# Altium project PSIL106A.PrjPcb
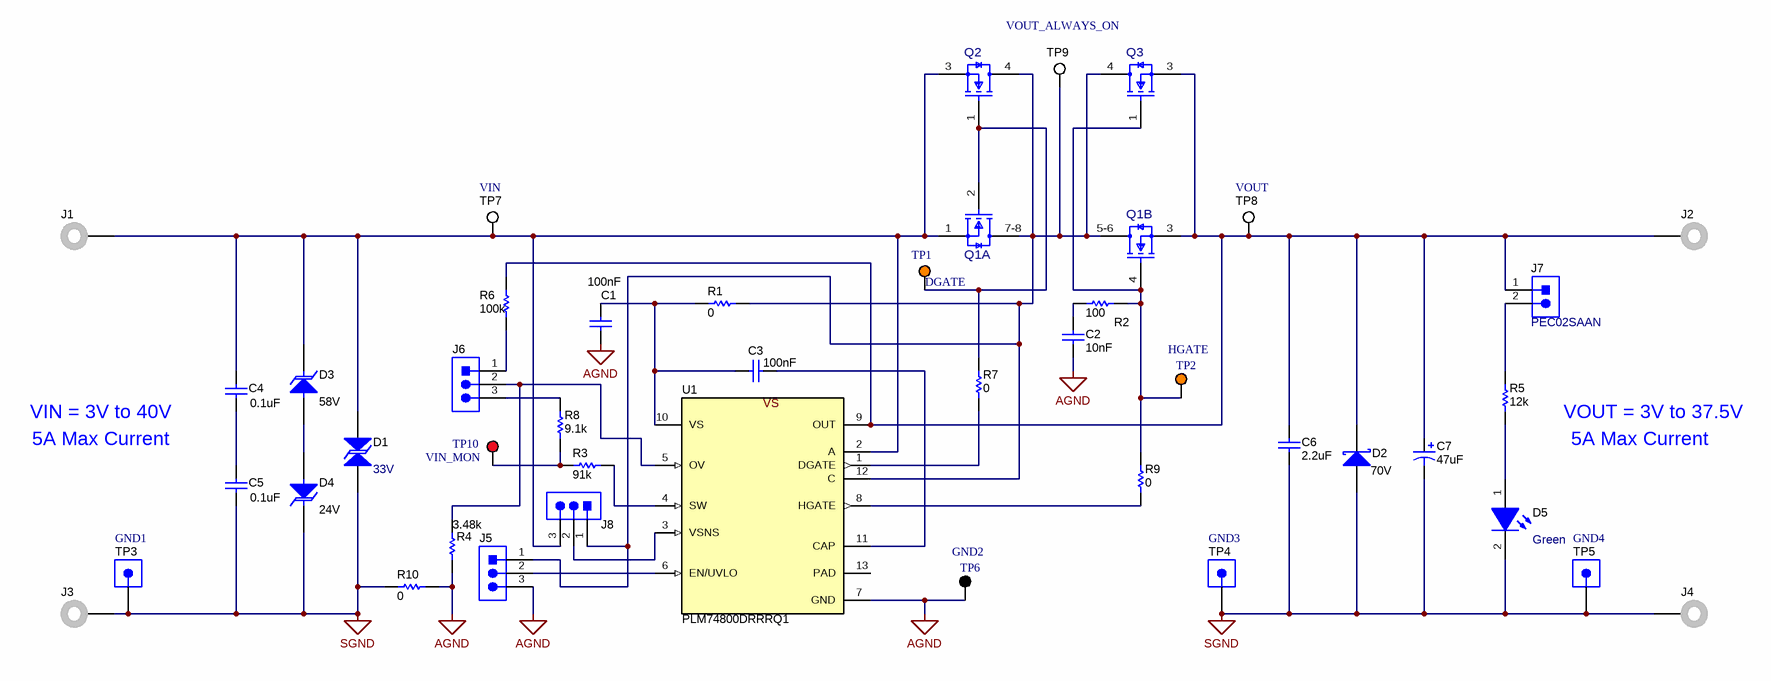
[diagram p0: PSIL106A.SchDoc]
CopyrightYear: 2019; PCB_Layout: Tessolve; PCB_Rev: A; PRJ_Customer: Public Release; PRJ_Engineer: Karikalan Selvaraj; PRJ_Number: PSIL106; PRJ_Title: LM74800EVM-CD; SCH_Rev: A; TechSupport: http://www.ti.com/support; TID: N/A
2 sheets, 64 parts. Net scope: global (net labels, ports and power ports of the same name join across sheets).
Board file: PSIL106A.PcbDoc
Sheets:
  PSIL106A.SchDoc
  PSIL106A_HW.SchDoc

## Sheet PSIL106A.SchDoc
size 431 x 279 mm; Date: Not shown in title block; ApprovedBy: Not shown in title block; CheckedBy: Not shown in title block; Author: Not shown in title block; CompanyName: Not shown in title block; Engineer: Not shown in title block; Organization: Not shown in title block; Address1: Not shown in title block; Address2: Not shown in title block; Address3: Not shown in title block; Address4: Not shown in title block; DocumentNumber: 1; Revision: Use project parameter SCH_Rev; SheetNumber: 1; SheetTotal: 2; PageSetup: Record=PageOptions¦CenterHorizontal=True¦CenterVertical=True¦PrintScale=0.62¦XCorrection=1.00¦YCorrection=1.00¦PrintKind=0¦BorderSize=5000000¦LeftOffset=0¦BottomOffset=0¦Orientation=2¦PaperLength=1000¦PaperWidth=1000¦Scale=100¦PaperSource=15¦PrintQuality=600¦MediaType=1¦DitherType=10¦PrintScaleMode=1¦PaperKind=Letter

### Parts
C1  Cap_F: 100nF  [0603]  (hidden comment: GRM188R72A104KA35J)
C2  Cap_F: 10nF  [0603]  (hidden comment: CGA3E2X7R2A103K080AA)
C3  Cap_F: 100nF  [0603]  (hidden comment: CGA3E2X7R1E104K080AA)
C4  ValueDisplayed: 0.1uF  [1206_180]  (hidden comment: CGA5L2X7R2A104K160AA)
C5  ValueDisplayed: 0.1uF  [1206_180]  (hidden comment: CGA5L2X7R2A104K160AA)
C6  ValueDisplayed: 2.2uF  [1210_210]  (hidden comment: CMP-0009084-1)
C7  ValueDisplayed: 47uF  [SM_RADIAL_F]  (hidden comment: EEE-FK1J470P)
D1  value 33V  [SMB-Bi]  (hidden comment: SMBJ33CA-13-F)
D2  value 70V  [SMA]  (hidden comment: B170-13-F)
D3  value 58V  [SMB]  (hidden comment: CMP-0005583-3)
D4  value 24V  [SMB]  (hidden comment: CMP-0005557-4)
D5  value Green  [LED_LTST-C190]  (hidden comment: LTST-C190GKT)
J1  CMP-0055166-2  [Keystone575-8]  (value not drawn)
J2  CMP-0055166-2  [Keystone575-8]  (value not drawn)
J3  CMP-0055166-2  [Keystone575-8]  (value not drawn)
J4  CMP-0055166-2  [Keystone575-8]  (value not drawn)
J5  PEC03SAAN  [CONN_PEC03SAAN]  (value not drawn)
J6  PEC03SAAN  [CONN_PEC03SAAN]  (value not drawn)
J7  PEC02SAAN  [CONN_PEC02SAAN]
J8  PEC03SAAN  [CONN_PEC03SAAN]  (value not drawn)
Q1  NVMFD5C672NLT1G  [FP-NVMFD5C672NLT1G_DFN8_5X6-MFG]  (value not drawn)  (parts A,B of 2)
Q2  IPD100N06S4-03  [FP-IPD100N06S4-03_PG-TO252-3-MFG]  (value not drawn)
Q3  IPD100N06S4-03  [FP-IPD100N06S4-03_PG-TO252-3-MFG]  (value not drawn)
R1  ValueDisplayed: 0  [0402]  (hidden comment: RK73Z1ETTP)
R2  ValueDisplayed: 100  [0603]  (hidden comment: CRCW0603100RJNEA)
R3  ValueDisplayed: 91k  [0603]  (hidden comment: CRCW060391K0JNEA)
R4  ValueDisplayed: 3.48k  [0603]  (hidden comment: CRCW06033K48FKEA)
R5  ValueDisplayed: 12k  [0603]  (hidden comment: CRCW060312K0JNEA)
R6  ValueDisplayed: 100k  [0603]  (hidden comment: CRCW0603100KFKEA)
R7  ValueDisplayed: 0  [0402]  (hidden comment: ERJ-2GE0R00X)
R8  ValueDisplayed: 9.1k  [0603]  (hidden comment: CRCW06039K10JNEA)
R9  ValueDisplayed: 0  [0402]  (hidden comment: ERJ-2GE0R00X)
R10  ValueDisplayed: 0  [0603]  (hidden comment: ERJ-3GEY0R00V)
TP1  5003  [Keystone5003]  (value not drawn)
TP2  5003  [Keystone5003]  (value not drawn)
TP3  CMP-0055161-1  [CONN_1040]  (value not drawn)
TP4  CMP-0055161-1  [CONN_1040]  (value not drawn)
TP5  CMP-0055161-1  [CONN_1040]  (value not drawn)
TP6  5001  [Keystone5001]  (value not drawn)
TP7  5015  [Testpoint_Keystone_Miniature]  (value not drawn)
TP8  5015  [Testpoint_Keystone_Miniature]  (value not drawn)
TP9  5015  [Testpoint_Keystone_Miniature]  (value not drawn)
TP10  5000  [Keystone5000]  (value not drawn)
U1  PLM74800DRRRQ1  [DRR0012E]

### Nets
AGND: C1.2 C2.2 J5.3 R4.1 R10.2 TP6.1 U1.7(GND)
SGND: C5.2 C6.2 C7.2(-) D1.1 D2.2(A) D4.1(K) D5.2(K) J3.1 J4.1 R10.1 TP3.1 TP4.1 TP5.1
NetC1_1: C1.1 C3.2 R1.1 U1.10(VS)
NetC2_1: C2.1 R2.1
NetC3_1: C3.1 U1.11(CAP)
NetC4_1: C4.1 D1.2 D3.1(K) J1.1 J8.3 Q1.1(S1) Q2.3(SOURCE) TP7.1 U1.2(A)
NetC4_2: C4.2 C5.1
NetC6_1: C6.1 C7.1(+) D2.1(K) J2.1 J7.1 Q1.3(S2) Q3.3(SOURCE) R6.2 TP8.1 U1.9(OUT)
NetD3_2: D3.2(A) D4.2(A)
NetD5_1: D5.1(A) R5.1
NetJ5_1: J5.1 J8.1 Q1.5-6(D2) Q1.7-8(D1) Q2.4(DRAIN) Q3.4(DRAIN) R1.2 TP9.1 U1.12(C)
NetJ5_2: J5.2 U1.6(EN/UVLO)
NetJ6_1: J6.1 R6.1
NetJ6_2: J6.2 R4.2 U1.5(OV)
NetJ6_3: J6.3 R8.2
NetJ7_2: J7.2 R5.2
NetJ8_2: J8.2 U1.3(VSNS)
NetQ1_2: Q1.2(G1) Q2.1(GATE) R7.2 TP1.1
NetQ1_4: Q1.4(G2) Q3.1(GATE) R2.2 R9.2 TP2.1
NetR3_1: R3.1 R8.1 TP10.1
NetR3_2: R3.2 U1.4(SW)
NetR7_1: R7.1 U1.1(DGATE)
NetR9_1: R9.1 U1.8(HGATE)

Not connected (* = marked no-connect by the designer): U1 13(PAD)

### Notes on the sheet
- VOUT_ALWAYS_ON
- (near TP7) VIN
- (near TP8) VOUT
- (near TP1) DGATE
- (near TP2) HGATE
- VIN = 3V to 40V
- VOUT = 3V to 37.5V
- 5A Max Current
- (near TP10) VIN_MON
- (near TP3) GND1
- (near TP6) GND2
- (near TP4) GND3
- (near TP5) GND4
- Labels drawn without touching a wire or pin: VS

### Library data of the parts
C1 = CMP-0007470-5: CAP, CERM, 0.1 uF, 100 V, +/- 10%, X7R, 0603; Manufacturer: MuRata; TaMin_C: -55°C; Polarized: N; SizeAreaWB_mm2: 4.68; Value1: Unknown; U/M: EA; Value: 0.1uF; TaMax_C: 125°C; SizeZ_mm: 1; SizeX_mm: 1.6; SizeY_mm: 0.8; Value2: 100V; SizeArea_mm2: 1.28; AEC Category: Q200
C2 = CMP-0007082-4: CAP, CERM, 0.01 uF, 100 V, +/- 10%, X7R, AEC-Q200 Grade 1, 0603; Manufacturer: TDK; TaMin_C: -55°C; ESR_ohm: 0.235428; Polarized: N; SizeAreaWB_mm2: 4.68; Value1: 0.235428 ohm; U/M: EA; Value: 0.01uF; TaMax_C: 125°C; SizeZ_mm: 1; SizeX_mm: 1.6; SizeY_mm: 0.8; Value2: 100V; SizeArea_mm2: 1.28; AEC Qualified: Y; IRMS_A: 396.995mA; AEC Category: Q200
C3 = CMP-0007077-5: CAP, CERM, 0.1 uF, 25 V, +/- 10%, X7R, AEC-Q200 Grade 1, 0603; Manufacturer: TDK; TaMin_C: -55°C; Polarized: N; SizeAreaWB_mm2: 4.68; Value1: Unknown; U/M: EA; Value: 0.1uF; TaMax_C: 125°C; SizeZ_mm: 1; SizeX_mm: 1.6; SizeY_mm: 0.8; Value2: 25V; SizeArea_mm2: 1.28; AEC Qualified: Y; AEC Category: Q200
C4 C5 = CMP-0008778-2: CAP, CERM, 0.1 uF, 100 V, +/- 10%, X7R, AEC-Q200 Grade 1, 1206; Manufacturer: TDK; TaMin_C: -55°C; ESR_ohm: 0.030343; Polarized: N; SizeAreaWB_mm2: 10.92; Value1: 0.030343 ohm; U/M: EA; Value: 0.1uF; TaMax_C: 125°C; SizeZ_mm: 1.8; SizeX_mm: 3.2; SizeY_mm: 1.6; Value2: 100V; SizeArea_mm2: 5.12; AEC Qualified: Y; Cap_F: 100nF; IRMS_A: 1.33802A; AEC Grade: 1; AEC Category: Q200
C6 = CMP-0009084-1: CAP, CERM, 2.2 uF, 100 V, +/- 10%, X7R, 1210; PartNumber: C1210C225K1RACTU; Manufacturer: Kemet; Polarized: N; CompType: Capacitor; Value: 2.2uF; U/M: EA; Cap_F: 2.2µF; Value1: Unknown; VDC_V: 100V; TaMin_C: -55°C; TaMax_C: 125°C; Cap_Case: 1210; SizeArea_mm2: 8; SizeAreaWB_mm2: 14.7; SizeX_mm: 3.2; SizeY_mm: 2.5; SizeZ_mm: 2.1; AEC Category: Q200
C7 = CMP-0011192-2: CAP, AL, 47 uF, 63 V, +/- 20%, 0.65 ohm, AEC-Q200 Grade 2, SMD; Manufacturer: Panasonic; TaMin_C: -55°C; ESR_ohm: 0.65; Polarized: Y; SizeAreaWB_mm2: 123.6; U/M: EA; Value: 47uF; TaMax_C: 105°C; SizeZ_mm: 10.2; SizeX_mm: 10; SizeY_mm: 8.3; Cap_Case: F; Value2: 63V; SizeArea_mm2: 83; CompType: Capacitor; Cap_F: 47µF; IRMS_A: 250mA; AEC Grade: 2; AEC Category: Q200
D1 = CMP-0005564-3: Diode, TVS, Bi, 33 V, SMB; Manufacturer: Diodes Inc.; SizeX_mm: 5.6; Ppk: 600W; SizeAreaWB_mm2: 44.156; SizeZ_mm: 2.6; SizeArea_mm2: 21.336; SizeY_mm: 3.81; AEC Category: Q101
D2 = CMP-0028391-2: Diode, Schottky, 70 V, 1 A, SMA; Manufacturer: Diodes Inc.; SizeAreaWB_mm2: 37.3428; RJC_CperW: 25; Io_A: 1A; AEC Category: Q101; Green_Lifecycle: Active; SizeZ_mm: 2.87; Vf_V: 790mV; SizeY_mm: 2.92; Green_REACh: Passed; Value2: 0.79V; SizeX_mm: 5.59; TJmax_C: 150°C; SizeArea_mm2: 16.3228
D3 = CMP-0005583-3: Diode, TVS, Uni, 58 V, 93.6 Vc, SMB; PartNumber: SMBJ58A-13-F; Manufacturer: Diodes Inc.; Value1: 600W; SizeAreaWB_mm2: 44.156; SizeArea_mm2: 21.336; SizeX_mm: 5.6; SizeY_mm: 3.81; SizeZ_mm: 2.6; AEC Category: Q101; Vbr_Max: 74.6V; Vbr_Min: 64.4V; Ipp: 6.4A; Vc: 93.6V
D4 = CMP-0005557-4: Diode, TVS, Uni, 24 V, 38.9 Vc, SMB; PartNumber: SMBJ24A-13-F; Manufacturer: Diodes Inc.; Value1: 600W; SizeAreaWB_mm2: 44.156; SizeArea_mm2: 21.336; SizeX_mm: 5.6; SizeY_mm: 3.81; SizeZ_mm: 2.6; AEC Category: Q101; Vbr_Max: 30.7V; Vbr_Min: 26.7V; Vc: 38.9V; Ipp: 15.4A
D5 = CMP-0002827-3: LED, Green, SMD; Manufacturer: Lite-On; Power_TotalModule: 100mW; Value2: 2.1V; Io_A: 20mA; Value1: 0.1W
J1-J4 = CMP-0055166-2: Standard Banana Jack, Uninsulated, 8.9mm; PartNumber: 575-8; Manufacturer: Keystone; CT: TRUE; Green_REACh: Passed; CNHeader: FALSE; Green_Lifecycle: Active
J5 J6 J8 = CMP-0002338-1: Header, 100mil, 3x1, Tin, TH; Manufacturer: Sullins Connector Solutions; CNHeader: TRUE; Current_A: 3A; Green_Lifecycle: Not Set; Shrouded: N; Gender: Male; Green_REACh: Incomplete; Voltage_V: 1.8kV; Row_Count: 1; Pitch_mm: 2.54; CT: FALSE; Cert_UL: Y
J7 = CMP-0002337-1: Header, 100mil, 2x1, Tin, TH; Manufacturer: Sullins Connector Solutions; CNHeader: TRUE; Current_A: 3A; Green_Lifecycle: Not Set; Shrouded: N; Gender: Male; Green_REACh: Incomplete; Voltage_V: 1.8kV; Row_Count: 1; Pitch_mm: 2.54; CT: FALSE; Cert_UL: Y
Q1 = CMP-0088121-1: Dual N-Channel MOSFET, 49 A, 60 V, 8-Pin DFN; Manufacturer: ON Semiconductor; PartNumber: NVMFD5C650NL; QgTyp_nC: 12.3nC @ 10V; AEC Qualified: Yes; SizeZ_mm: 1.1mm; VdsMax_V: 60V; ChMode: False; Vgs_V: 20V; Rdson45_ohm: 0.0134; IdsMax_A: 11A
Q2 Q3 = CMP-0086637-1: INF-MOSFET-N-3; Manufacturer: Infineon; QgTyp_nC: 99nC @ 10V; Vgs_V: 20V; AEC Qualified: Yes; IdsMax_A: 100A; ChMode: False; VdsMax_V: 60V; SizeZ_mm: 2.5mm; Rdson45_ohm: 2.8m
R1 = CMP-0027007-2: RES, 0, 5%, 0.063 W, AEC-Q200 Grade 0, 0402; Manufacturer: KOA Speer; Power_W: 63mW; TempCo: ppm/C; Value_Code: 0000; U/M: EA; Value: 0; EIA_Code: E24; SizeX_mm: 1; SizeY_mm: 0.5; SizeZ_mm: 0.6; Value2: 0.063W; AEC Qualified: Y; AEC Category: Q200
R2 = CMP-0025700-4: RES, 100, 5%, 0.1 W, AEC-Q200 Grade 0, 0603; Manufacturer: Vishay-Dale; Power_W: 100mW; TempCo: 200 ppm/C; Value_Code: 100R; Value: 100; EIA_Code: E24; SizeX_mm: 1.6; SizeY_mm: 0.8; SizeZ_mm: 1; Value2: 0.1W; SizeArea_mm2: 1.28; AEC Qualified: Y; VDC_V: 75V; AEC Category: Q200; AEC Grade: 0
R3 = CMP-0025867-4: RES, 91 k, 5%, 0.1 W, AEC-Q200 Grade 0, 0603; Manufacturer: Vishay-Dale; Power_W: 100mW; TempCo: 200 ppm/C; Value_Code: 91k0; Value: 91k; EIA_Code: E24; SizeX_mm: 1.6; SizeY_mm: 0.8; SizeZ_mm: 1; Value2: 0.1W; SizeArea_mm2: 1.28; AEC Qualified: Y; VDC_V: 75V; AEC Category: Q200; AEC Grade: 0
R4 = CMP-0022377-4: RES, 3.48 k, 1%, 0.1 W, AEC-Q200 Grade 0, 0603; Manufacturer: Vishay-Dale; Power_W: 100mW; TempCo: 100 ppm/C; Value_Code: 3k48; Value: 3.48k; EIA_Code: E96; SizeX_mm: 1.6; SizeY_mm: 0.8; SizeZ_mm: 1; Value2: 0.1W; SizeArea_mm2: 1.28; AEC Qualified: Y; VDC_V: 75V; AEC Category: Q200; AEC Grade: 0
R5 = CMP-0025711-4: RES, 12 k, 5%, 0.1 W, AEC-Q200 Grade 0, 0603; Manufacturer: Vishay-Dale; Power_W: 100mW; TempCo: 200 ppm/C; Value_Code: 12k0; Value: 12k; EIA_Code: E24; SizeX_mm: 1.6; SizeY_mm: 0.8; SizeZ_mm: 1; Value2: 0.1W; SizeArea_mm2: 1.28; AEC Qualified: Y; VDC_V: 75V; AEC Category: Q200; AEC Grade: 0
R6 = CMP-0021990-4: RES, 100 k, 1%, 0.1 W, AEC-Q200 Grade 0, 0603; Manufacturer: Vishay-Dale; Power_W: 100mW; TempCo: 100 ppm/C; Value: 100k; EIA_Code: E96; SizeX_mm: 1.6; SizeY_mm: 0.8; SizeZ_mm: 1; Value2: 0.1W; SizeArea_mm2: 1.28; AEC Qualified: Y; VDC_V: 75V; AEC Category: Q200; AEC Grade: 0
R7 R9 = CMP-0026992-3: RES, 0, 5%, 0.1 W, AEC-Q200 Grade 0, 0402; Manufacturer: Panasonic; Power_W: 100mW; TempCo: 600 ppm/C; Value_Code: 0000; Value: 0; EIA_Code: E24; SizeX_mm: 1; SizeY_mm: 0.5; SizeZ_mm: 0.6; Value2: 0.1W; AEC Qualified: Y; VDC_V: 50V; AEC Category: Q200; SizeAreaWB_mm2: 3
R8 = CMP-0025869-4: RES, 9.1 k, 5%, 0.1 W, AEC-Q200 Grade 0, 0603; Manufacturer: Vishay-Dale; Power_W: 100mW; TempCo: 200 ppm/C; Value_Code: 9k10; Value: 9.1k; EIA_Code: E24; SizeX_mm: 1.6; SizeY_mm: 0.8; SizeZ_mm: 1; Value2: 0.1W; SizeArea_mm2: 1.28; AEC Qualified: Y; VDC_V: 75V; AEC Category: Q200; AEC Grade: 0
R10 = CMP-0025874-4: RES, 0, 5%, 0.1 W, AEC-Q200 Grade 0, 0603; Manufacturer: Panasonic; Power_W: 100mW; TempCo: 600 ppm/C; Value_Code: 0000; Value: 0; EIA_Code: E24; SizeX_mm: 1.6; SizeY_mm: 0.8; SizeZ_mm: 1; Value2: 0.1W; SizeArea_mm2: 1.28; AEC Qualified: Y; VDC_V: 50V; AEC Category: Q200; SizeAreaWB_mm2: 4.68
TP1 TP2 = CMP-0055140-1: Test Point, Miniature, Orange, TH; Manufacturer: Keystone; CNHeader: FALSE; Green_Lifecycle: Active; Green_REACh: Passed; ContactFinish: Silver; CT: TRUE
TP3-TP5 = CMP-0055161-1: TEST POINT SLOTTED .118", TH; PartNumber: 1040; Manufacturer: Keystone; CNHeader: FALSE; Green_Lifecycle: Active; Green_REACh: Passed; CT: TRUE
TP6 = CMP-0055138-1: Test Point, Miniature, Black, TH; Manufacturer: Keystone; CNHeader: FALSE; Green_Lifecycle: Active; Green_REACh: Passed; ContactFinish: Silver; CT: TRUE
TP7-TP9 = 5015: Test Point, Miniature, SMT; Manufacturer: Keystone; CompType: Test Point Loop
TP10 = CMP-0055137-1: Test Point, Miniature, Red, TH; Manufacturer: Keystone; CNHeader: FALSE; Green_Lifecycle: Active; Green_REACh: Passed; ContactFinish: Silver; CT: TRUE
U1 = CMP-0860384-3: Ideal Diode Controller with Load Dump Protection, DRR0012E (WSON-12); Manufacturer: Texas Instruments; AEC Category: Q200; SizeY_mm: 3; SizeArea_mm2: 9; CompType: IC; SizeZ_mm: 0.8; AEC Qualified: Y; SizeAreaWB_mm2: 16

## Sheet PSIL106A_HW.SchDoc
size 431 x 279 mm; Date: Not shown in title block; ApprovedBy: Not shown in title block; CheckedBy: Not shown in title block; Author: Not shown in title block; CompanyName: Not shown in title block; Engineer: Not shown in title block; Organization: Not shown in title block; Address1: Not shown in title block; Address2: Not shown in title block; Address3: Not shown in title block; Address4: Not shown in title block; DocumentNumber: 1; Revision: Use project parameter SCH_Rev; SheetNumber: 2; SheetTotal: 2; PageSetup: Record=PageOptions¦CenterHorizontal=True¦CenterVertical=True¦PrintScale=1.00¦XCorrection=1.00¦YCorrection=1.00¦PrintKind=0¦BorderSize=5000000¦LeftOffset=0¦BottomOffset=0¦Orientation=2¦PaperLength=1000¦PaperWidth=1000¦Scale=100¦PaperSource=15¦PrintQuality=600¦MediaType=1¦DitherType=10¦PaperKind=Letter¦PrintScaleMode=1
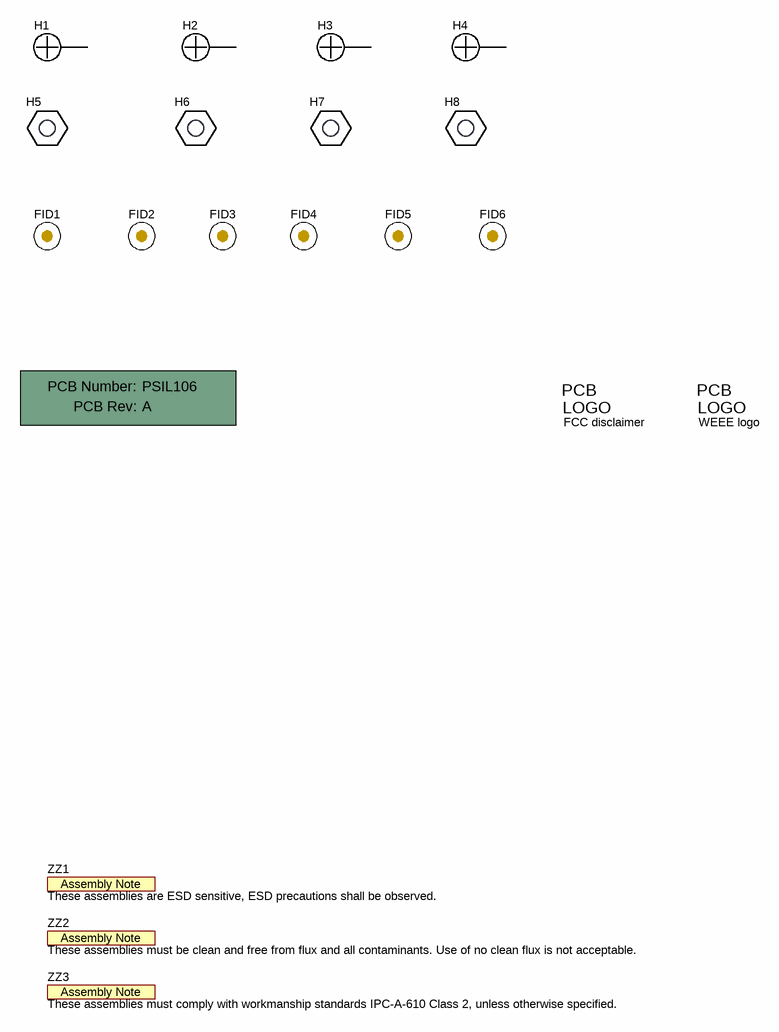
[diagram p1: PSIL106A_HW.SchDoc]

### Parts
!PCB1  Printed Circuit Board  (value not drawn)  (mechanical)
FID1  Fiducial  [Fiducial10-20]  (value not drawn)
FID2  Fiducial  [Fiducial10-20]  (value not drawn)
FID3  Fiducial  [Fiducial10-20]  (value not drawn)
FID4  Fiducial  [Fiducial10-20]  (value not drawn)
FID5  Fiducial  [Fiducial10-20]  (value not drawn)
FID6  Fiducial  [Fiducial10-20]  (value not drawn)
H1  NY PMS 440 0025 PH  [NY PMS 440 0025 PH]  (value not drawn)
H2  NY PMS 440 0025 PH  [NY PMS 440 0025 PH]  (value not drawn)
H3  NY PMS 440 0025 PH  [NY PMS 440 0025 PH]  (value not drawn)
H4  NY PMS 440 0025 PH  [NY PMS 440 0025 PH]  (value not drawn)
H5  CMP-0003610-1  [Keystone_1902C]  (value not drawn)
H6  CMP-0003610-1  [Keystone_1902C]  (value not drawn)
H7  CMP-0003610-1  [Keystone_1902C]  (value not drawn)
H8  CMP-0003610-1  [Keystone_1902C]  (value not drawn)
Logo3  FCC disclaimer  [FCC_disclaimer]  (no BOM)
Logo4  WEEE logo  [WEEE_Minimum]  (no BOM)
ZZ1  These assemblies are ESD sensitive, ESD precautions shall be observed.  [AssemblyNote]  (no BOM)
ZZ2  These assemblies must be clean and free from flux and all contaminants. Use of no clean flux is not acceptable.  [AssemblyNote]  (no BOM)
ZZ3  These assemblies must comply with workmanship standards IPC-A-610 Class 2, unless otherwise specified.  [AssemblyNote]  (no BOM)

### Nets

Not connected (* = marked no-connect by the designer): H1 1; H2 1; H3 1; H4 1

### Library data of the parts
!PCB1 = CMP-0003618-2: Manufacturer: Any; PartNumber: PSIL106; CompType: PCB
FID1-FID6 = CMP-0077181-1: Fiducial mark.  There is nothing to buy or mount.
H1-H4 = CMP-0003617-1: Machine Screw, Round, #4-40 x 1/4, Nylon, Philips panhead; Manufacturer: B&F Fastener Supply; CompType: Hardware
H5-H8 = CMP-0003610-1: Standoff, Hex, 0.5"L #4-40 Nylon; Manufacturer: Keystone; PartNumber: 1902C; CompType: Hardware
Logo3 = CMP-0074847-1: FCC_disclaimer; Library Reference: Logo
Logo4 = CMP-0074769-1
ZZ1 = CMP-0077236-1
ZZ2 = CMP-0077237-1
ZZ3 = CMP-0077238-1

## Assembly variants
001: not fitted C8 C9 C10 D3 D4 FID1 FID2 FID3 FID4 FID5 FID6 Q2 Q3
